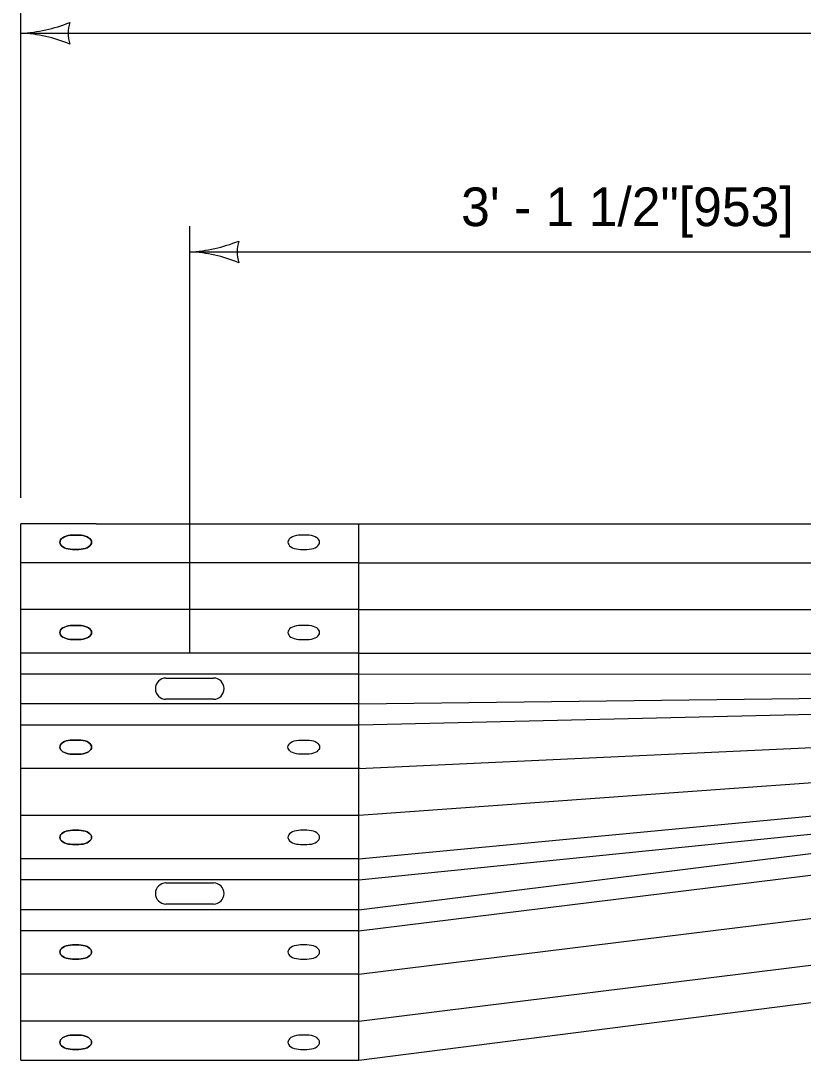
# Model space of a CAD drawing. Extents: x 49991 to 50160, y 49948 to 50051.
# Drawn here: x 50012.117 to 50013.332, y 49992.648 to 49994.263 of the extents above; entities that cross this region are included whole.
import ezdxf

# ---------------------------------------------------------------- set-up
doc = ezdxf.new("R2010")
doc.units = 0
for name, color, linetype in [('Level 1', 7, 'Continuous'), ('Level 2', 7, 'Continuous'), ('Level 3', 7, 'Continuous')]:
    doc.layers.add(name, color=color, linetype=linetype)

msp = doc.modelspace()

# ---------------------------------------------------------------- linework, layer by layer
at = {"layer": 'Level 1'}
for p, q in [((50012.1168, 49992.6481), (50012.1168, 49993.4814)), ((50012.234, 49993.4814), (50015.7668, 49993.4812)), ((50012.6417, 49992.6481), (50012.6417, 49993.4814)), ((50012.207, 49993.4637), (50012.1972, 49993.4637)), ((50012.1972, 49993.4637), (50012.207, 49993.4637)), ((50012.5613, 49993.4637), (50012.5515, 49993.4637)), ((50012.1972, 49993.4416), (50012.207, 49993.4416)), ((50012.207, 49993.4416), (50012.1972, 49993.4416)), ((50012.5515, 49993.4416), (50012.5613, 49993.4416)), ((50012.6417, 49993.4206), (50012.1168, 49993.4206)), ((50012.6417, 49993.4206), (50015.7668, 49993.4206)), ((50012.6417, 49993.3481), (50012.1168, 49993.3481)), ((50012.6417, 49993.3481), (50015.7668, 49993.3478)), ((50012.207, 49993.3235), (50012.1972, 49993.3235)), ((50012.1972, 49993.3235), (50012.207, 49993.3235)), ((50012.5613, 49993.3235), (50012.5515, 49993.3235)), ((50012.1972, 49993.3014), (50012.207, 49993.3014)), ((50012.207, 49993.3014), (50012.1972, 49993.3014)), ((50012.5515, 49993.3014), (50012.5613, 49993.3014)), ((50012.6417, 49993.2803), (50012.1168, 49993.2803)), ((50012.6417, 49993.2803), (50015.7668, 49993.2808)), ((50012.6417, 49993.2477), (50012.1168, 49993.2477)), ((50012.6417, 49993.2477), (50013.8943, 49993.2482)), ((50012.3423, 49993.2417), (50012.4162, 49993.2417)), ((50015.2419, 49993.2294), (50012.6417, 49993.1687)), ((50012.6417, 49993.1011), (50015.2419, 49993.2221)), ((50012.6417, 49993.2014), (50013.8983, 49993.2174)), ((50015.2419, 49993.2146), (50012.6417, 49993.0283)), ((50012.641, 49993.2014), (50012.1168, 49993.2014)), ((50012.4162, 49993.2088), (50012.3423, 49993.2088)), ((50012.6417, 49992.9608), (50015.2419, 49993.2073)), ((50012.6424, 49993.1687), (50012.1168, 49993.1687)), ((50012.6417, 49992.8492), (50015.2419, 49993.1697)), ((50012.1972, 49993.1454), (50012.207, 49993.1454)), ((50012.207, 49993.1454), (50012.1972, 49993.1454)), ((50012.5515, 49993.1454), (50012.5613, 49993.1454)), ((50012.207, 49993.1234), (50012.1972, 49993.1234)), ((50012.1972, 49993.1234), (50012.207, 49993.1234)), ((50012.5613, 49993.1234), (50012.5515, 49993.1234)), ((50012.6417, 49992.7816), (50015.2419, 49993.1024)), ((50012.6437, 49993.1011), (50012.1168, 49993.1011)), ((50012.6417, 49992.928), (50013.8855, 49993.0539)), ((50012.6417, 49992.8819), (50013.896, 49993.0379)), ((50012.6417, 49993.0283), (50012.1168, 49993.0283)), ((50012.6417, 49992.7088), (50015.2419, 49993.0299)), ((50012.207, 49993.0052), (50012.1972, 49993.0052)), ((50012.1972, 49993.0052), (50012.207, 49993.0052)), ((50012.5613, 49993.0052), (50012.5515, 49993.0052)), ((50012.1972, 49992.9832), (50012.207, 49992.9832)), ((50012.207, 49992.9832), (50012.1972, 49992.9832)), ((50012.5515, 49992.9832), (50012.5613, 49992.9832)), ((50012.6417, 49992.6481), (50015.2419, 49992.9795)), ((50012.6417, 49992.9608), (50012.1168, 49992.9608)), ((50012.6417, 49992.928), (50012.1168, 49992.928)), ((50012.3423, 49992.9234), (50012.4162, 49992.9234)), ((50012.6417, 49992.8819), (50012.1168, 49992.8819)), ((50012.4162, 49992.8906), (50012.3423, 49992.8906)), ((50012.6417, 49992.8492), (50012.1168, 49992.8492)), ((50012.207, 49992.8272), (50012.1972, 49992.8272)), ((50012.1972, 49992.8272), (50012.207, 49992.8272)), ((50012.5613, 49992.8272), (50012.5515, 49992.8272)), ((50012.1972, 49992.8051), (50012.207, 49992.8051)), ((50012.207, 49992.8051), (50012.1972, 49992.8051)), ((50012.5515, 49992.8051), (50012.5613, 49992.8051)), ((50012.6417, 49992.7816), (50012.1168, 49992.7816)), ((50012.6417, 49992.7088), (50012.1168, 49992.7088)), ((50012.207, 49992.687), (50012.1972, 49992.687)), ((50012.1972, 49992.687), (50012.207, 49992.687)), ((50012.5613, 49992.687), (50012.5515, 49992.687)), ((50012.1972, 49992.6649), (50012.207, 49992.6649)), ((50012.207, 49992.6649), (50012.1972, 49992.6649)), ((50012.5515, 49992.6649), (50012.5613, 49992.6649))]:
    msp.add_line(p, q, dxfattribs=at)
for points in [[(50012.234, 49993.4814), (50012.1168, 49993.4814)], [(50012.1972, 49993.4637), (50012.1937, 49993.4635), (50012.1904, 49993.463), (50012.1873, 49993.4622), (50012.1845, 49993.4611), (50012.1821, 49993.4597), (50012.1801, 49993.4582), (50012.1787, 49993.4564), (50012.1778, 49993.4546), (50012.1777, 49993.4545)], [(50012.1777, 49993.4545), (50012.1778, 49993.4546), (50012.1787, 49993.4564), (50012.1801, 49993.4582), (50012.1821, 49993.4597), (50012.1845, 49993.4611), (50012.1873, 49993.4622), (50012.1904, 49993.463), (50012.1937, 49993.4635), (50012.1972, 49993.4637)], [(50012.2264, 49993.4545), (50012.2264, 49993.4546), (50012.2255, 49993.4564), (50012.2241, 49993.4582), (50012.2221, 49993.4597), (50012.2197, 49993.4611), (50012.2168, 49993.4622), (50012.2137, 49993.463), (50012.2104, 49993.4635), (50012.207, 49993.4637)], [(50012.207, 49993.4637), (50012.2104, 49993.4635), (50012.2137, 49993.463), (50012.2168, 49993.4622), (50012.2197, 49993.4611), (50012.2221, 49993.4597), (50012.2241, 49993.4582), (50012.2255, 49993.4564), (50012.2264, 49993.4546), (50012.2264, 49993.4545)], [(50012.5515, 49993.4637), (50012.5481, 49993.4635), (50012.5448, 49993.463), (50012.5416, 49993.4622), (50012.5388, 49993.4611), (50012.5364, 49993.4597), (50012.5344, 49993.4582), (50012.533, 49993.4564), (50012.5321, 49993.4546), (50012.5321, 49993.4545)], [(50012.5808, 49993.4545), (50012.5807, 49993.4546), (50012.5798, 49993.4564), (50012.5784, 49993.4582), (50012.5764, 49993.4597), (50012.574, 49993.4611), (50012.5712, 49993.4622), (50012.5681, 49993.463), (50012.5648, 49993.4635), (50012.5613, 49993.4637)], [(50012.1777, 49993.4545), (50012.1775, 49993.4527), (50012.1778, 49993.4507), (50012.1787, 49993.4489), (50012.1801, 49993.4471), (50012.1821, 49993.4456), (50012.1845, 49993.4442), (50012.1873, 49993.4431), (50012.1904, 49993.4423), (50012.1937, 49993.4418), (50012.1972, 49993.4416)], [(50012.1972, 49993.4416), (50012.1937, 49993.4418), (50012.1904, 49993.4423), (50012.1873, 49993.4431), (50012.1845, 49993.4442), (50012.1821, 49993.4456), (50012.1801, 49993.4471), (50012.1787, 49993.4489), (50012.1778, 49993.4507), (50012.1775, 49993.4527), (50012.1777, 49993.4545)], [(50012.207, 49993.4416), (50012.2104, 49993.4418), (50012.2137, 49993.4423), (50012.2168, 49993.4431), (50012.2197, 49993.4442), (50012.2221, 49993.4456), (50012.2241, 49993.4471), (50012.2255, 49993.4489), (50012.2264, 49993.4507), (50012.2267, 49993.4527), (50012.2264, 49993.4545)], [(50012.2264, 49993.4545), (50012.2267, 49993.4527), (50012.2264, 49993.4507), (50012.2255, 49993.4489), (50012.2241, 49993.4471), (50012.2221, 49993.4456), (50012.2197, 49993.4442), (50012.2168, 49993.4431), (50012.2137, 49993.4423), (50012.2104, 49993.4418), (50012.207, 49993.4416)], [(50012.5321, 49993.4545), (50012.5318, 49993.4527), (50012.5321, 49993.4507), (50012.533, 49993.4489), (50012.5344, 49993.4471), (50012.5364, 49993.4456), (50012.5388, 49993.4442), (50012.5416, 49993.4431), (50012.5448, 49993.4423), (50012.5481, 49993.4418), (50012.5515, 49993.4416)], [(50012.5613, 49993.4416), (50012.5648, 49993.4418), (50012.5681, 49993.4423), (50012.5712, 49993.4431), (50012.574, 49993.4442), (50012.5764, 49993.4456), (50012.5784, 49993.4471), (50012.5798, 49993.4489), (50012.5807, 49993.4507), (50012.581, 49993.4527), (50012.5808, 49993.4545)], [(50012.1972, 49993.3235), (50012.1937, 49993.3233), (50012.1904, 49993.3228), (50012.1873, 49993.322), (50012.1845, 49993.3209), (50012.1821, 49993.3195), (50012.1801, 49993.318), (50012.1787, 49993.3162), (50012.1778, 49993.3144), (50012.1775, 49993.3125), (50012.1778, 49993.3105), (50012.1787, 49993.3087), (50012.1801, 49993.3069), (50012.1821, 49993.3054), (50012.1845, 49993.304), (50012.1873, 49993.3029), (50012.1904, 49993.3021), (50012.1937, 49993.3016), (50012.1972, 49993.3014)], [(50012.1972, 49993.3014), (50012.1937, 49993.3016), (50012.1904, 49993.3021), (50012.1873, 49993.3029), (50012.1845, 49993.304), (50012.1821, 49993.3054), (50012.1801, 49993.3069), (50012.1787, 49993.3087), (50012.1778, 49993.3105), (50012.1775, 49993.3125), (50012.1778, 49993.3144), (50012.1787, 49993.3162), (50012.1801, 49993.318), (50012.1821, 49993.3195), (50012.1845, 49993.3209), (50012.1873, 49993.322), (50012.1904, 49993.3228), (50012.1937, 49993.3233), (50012.1972, 49993.3235)], [(50012.207, 49993.3014), (50012.2104, 49993.3016), (50012.2137, 49993.3021), (50012.2168, 49993.3029), (50012.2197, 49993.304), (50012.2221, 49993.3054), (50012.2241, 49993.3069), (50012.2255, 49993.3087), (50012.2264, 49993.3105), (50012.2267, 49993.3125), (50012.2264, 49993.3144), (50012.2255, 49993.3162), (50012.2241, 49993.318), (50012.2221, 49993.3195), (50012.2197, 49993.3209), (50012.2168, 49993.322), (50012.2137, 49993.3228), (50012.2104, 49993.3233), (50012.207, 49993.3235)], [(50012.207, 49993.3235), (50012.2104, 49993.3233), (50012.2137, 49993.3228), (50012.2168, 49993.322), (50012.2197, 49993.3209), (50012.2221, 49993.3195), (50012.2241, 49993.318), (50012.2255, 49993.3162), (50012.2264, 49993.3144), (50012.2267, 49993.3125), (50012.2264, 49993.3105), (50012.2255, 49993.3087), (50012.2241, 49993.3069), (50012.2221, 49993.3054), (50012.2197, 49993.304), (50012.2168, 49993.3029), (50012.2137, 49993.3021), (50012.2104, 49993.3016), (50012.207, 49993.3014)], [(50012.5515, 49993.3235), (50012.5481, 49993.3233), (50012.5448, 49993.3228), (50012.5416, 49993.322), (50012.5388, 49993.3209), (50012.5364, 49993.3195), (50012.5344, 49993.318), (50012.533, 49993.3162), (50012.5321, 49993.3144), (50012.5318, 49993.3125), (50012.5321, 49993.3105), (50012.533, 49993.3087), (50012.5344, 49993.3069), (50012.5364, 49993.3054), (50012.5388, 49993.304), (50012.5416, 49993.3029), (50012.5448, 49993.3021), (50012.5481, 49993.3016), (50012.5515, 49993.3014)], [(50012.5613, 49993.3014), (50012.5648, 49993.3016), (50012.5681, 49993.3021), (50012.5712, 49993.3029), (50012.574, 49993.304), (50012.5764, 49993.3054), (50012.5784, 49993.3069), (50012.5798, 49993.3087), (50012.5807, 49993.3105), (50012.581, 49993.3125), (50012.5807, 49993.3144), (50012.5798, 49993.3162), (50012.5784, 49993.318), (50012.5764, 49993.3195), (50012.574, 49993.3209), (50012.5712, 49993.322), (50012.5681, 49993.3228), (50012.5648, 49993.3233), (50012.5613, 49993.3235)], [(50012.1972, 49993.1234), (50012.1937, 49993.1236), (50012.1904, 49993.1241), (50012.1873, 49993.1249), (50012.1845, 49993.126), (50012.1821, 49993.1273), (50012.1801, 49993.1289), (50012.1787, 49993.1306), (50012.1778, 49993.1325), (50012.1775, 49993.1344), (50012.1777, 49993.1362)], [(50012.1777, 49993.1362), (50012.1775, 49993.1344), (50012.1778, 49993.1325), (50012.1787, 49993.1306), (50012.1801, 49993.1289), (50012.1821, 49993.1273), (50012.1845, 49993.126), (50012.1873, 49993.1249), (50012.1904, 49993.1241), (50012.1937, 49993.1236), (50012.1972, 49993.1234)], [(50012.1777, 49993.1362), (50012.1778, 49993.1363), (50012.1787, 49993.1382), (50012.1801, 49993.1399), (50012.1821, 49993.1415), (50012.1845, 49993.1429), (50012.1873, 49993.144), (50012.1904, 49993.1448), (50012.1937, 49993.1453), (50012.1972, 49993.1454)], [(50012.1972, 49993.1454), (50012.1937, 49993.1453), (50012.1904, 49993.1448), (50012.1873, 49993.144), (50012.1845, 49993.1429), (50012.1821, 49993.1415), (50012.1801, 49993.1399), (50012.1787, 49993.1382), (50012.1778, 49993.1363), (50012.1777, 49993.1362)], [(50012.207, 49993.1454), (50012.2104, 49993.1453), (50012.2137, 49993.1448), (50012.2168, 49993.144), (50012.2197, 49993.1429), (50012.2221, 49993.1415), (50012.2241, 49993.1399), (50012.2255, 49993.1382), (50012.2264, 49993.1363), (50012.2264, 49993.1362)], [(50012.2264, 49993.1362), (50012.2264, 49993.1363), (50012.2255, 49993.1382), (50012.2241, 49993.1399), (50012.2221, 49993.1415), (50012.2197, 49993.1429), (50012.2168, 49993.144), (50012.2137, 49993.1448), (50012.2104, 49993.1453), (50012.207, 49993.1454)], [(50012.2264, 49993.1362), (50012.2267, 49993.1344), (50012.2264, 49993.1325), (50012.2255, 49993.1306), (50012.2241, 49993.1289), (50012.2221, 49993.1273), (50012.2197, 49993.126), (50012.2168, 49993.1249), (50012.2137, 49993.1241), (50012.2104, 49993.1236), (50012.207, 49993.1234)], [(50012.207, 49993.1234), (50012.2104, 49993.1236), (50012.2137, 49993.1241), (50012.2168, 49993.1249), (50012.2197, 49993.126), (50012.2221, 49993.1273), (50012.2241, 49993.1289), (50012.2255, 49993.1306), (50012.2264, 49993.1325), (50012.2267, 49993.1344), (50012.2264, 49993.1362)], [(50012.5515, 49993.1234), (50012.5481, 49993.1236), (50012.5448, 49993.1241), (50012.5416, 49993.1249), (50012.5388, 49993.126), (50012.5364, 49993.1273), (50012.5344, 49993.1289), (50012.533, 49993.1306), (50012.5321, 49993.1325), (50012.5318, 49993.1344), (50012.5321, 49993.1362)], [(50012.5321, 49993.1362), (50012.5321, 49993.1363), (50012.533, 49993.1382), (50012.5344, 49993.1399), (50012.5364, 49993.1415), (50012.5388, 49993.1429), (50012.5416, 49993.144), (50012.5448, 49993.1448), (50012.5481, 49993.1453), (50012.5515, 49993.1454)], [(50012.5613, 49993.1454), (50012.5648, 49993.1453), (50012.5681, 49993.1448), (50012.5712, 49993.144), (50012.574, 49993.1429), (50012.5764, 49993.1415), (50012.5784, 49993.1399), (50012.5798, 49993.1382), (50012.5807, 49993.1363), (50012.5808, 49993.1362)], [(50012.5808, 49993.1362), (50012.581, 49993.1344), (50012.5807, 49993.1325), (50012.5798, 49993.1306), (50012.5784, 49993.1289), (50012.5764, 49993.1273), (50012.574, 49993.126), (50012.5712, 49993.1249), (50012.5681, 49993.1241), (50012.5648, 49993.1236), (50012.5613, 49993.1234)], [(50012.1972, 49993.0052), (50012.1937, 49993.0051), (50012.1904, 49993.0046), (50012.1873, 49993.0038), (50012.1845, 49993.0027), (50012.1821, 49993.0013), (50012.1801, 49992.9997), (50012.1787, 49992.998), (50012.1778, 49992.9961), (50012.1775, 49992.9942), (50012.1778, 49992.9923), (50012.1787, 49992.9904), (50012.1801, 49992.9887), (50012.1821, 49992.9871), (50012.1845, 49992.9858), (50012.1873, 49992.9847), (50012.1904, 49992.9839), (50012.1937, 49992.9834), (50012.1972, 49992.9832)], [(50012.1972, 49992.9832), (50012.1937, 49992.9834), (50012.1904, 49992.9839), (50012.1873, 49992.9847), (50012.1845, 49992.9858), (50012.1821, 49992.9871), (50012.1801, 49992.9887), (50012.1787, 49992.9904), (50012.1778, 49992.9923), (50012.1775, 49992.9942), (50012.1778, 49992.9961), (50012.1787, 49992.998), (50012.1801, 49992.9997), (50012.1821, 49993.0013), (50012.1845, 49993.0027), (50012.1873, 49993.0038), (50012.1904, 49993.0046), (50012.1937, 49993.0051), (50012.1972, 49993.0052)], [(50012.207, 49992.9832), (50012.2104, 49992.9834), (50012.2137, 49992.9839), (50012.2168, 49992.9847), (50012.2197, 49992.9858), (50012.2221, 49992.9871), (50012.2241, 49992.9887), (50012.2255, 49992.9904), (50012.2264, 49992.9923), (50012.2267, 49992.9942), (50012.2264, 49992.9961), (50012.2255, 49992.998), (50012.2241, 49992.9997), (50012.2221, 49993.0013), (50012.2197, 49993.0027), (50012.2168, 49993.0038), (50012.2137, 49993.0046), (50012.2104, 49993.0051), (50012.207, 49993.0052)], [(50012.207, 49993.0052), (50012.2104, 49993.0051), (50012.2137, 49993.0046), (50012.2168, 49993.0038), (50012.2197, 49993.0027), (50012.2221, 49993.0013), (50012.2241, 49992.9997), (50012.2255, 49992.998), (50012.2264, 49992.9961), (50012.2267, 49992.9942), (50012.2264, 49992.9923), (50012.2255, 49992.9904), (50012.2241, 49992.9887), (50012.2221, 49992.9871), (50012.2197, 49992.9858), (50012.2168, 49992.9847), (50012.2137, 49992.9839), (50012.2104, 49992.9834), (50012.207, 49992.9832)], [(50012.5515, 49993.0052), (50012.5481, 49993.0051), (50012.5448, 49993.0046), (50012.5416, 49993.0038), (50012.5388, 49993.0027), (50012.5364, 49993.0013), (50012.5344, 49992.9997), (50012.533, 49992.998), (50012.5321, 49992.9961), (50012.5318, 49992.9942), (50012.5321, 49992.9923), (50012.533, 49992.9904), (50012.5344, 49992.9887), (50012.5364, 49992.9871), (50012.5388, 49992.9858), (50012.5416, 49992.9847), (50012.5448, 49992.9839), (50012.5481, 49992.9834), (50012.5515, 49992.9832)], [(50012.5613, 49992.9832), (50012.5648, 49992.9834), (50012.5681, 49992.9839), (50012.5712, 49992.9847), (50012.574, 49992.9858), (50012.5764, 49992.9871), (50012.5784, 49992.9887), (50012.5798, 49992.9904), (50012.5807, 49992.9923), (50012.581, 49992.9942), (50012.5807, 49992.9961), (50012.5798, 49992.998), (50012.5784, 49992.9997), (50012.5764, 49993.0013), (50012.574, 49993.0027), (50012.5712, 49993.0038), (50012.5681, 49993.0046), (50012.5648, 49993.0051), (50012.5613, 49993.0052)], [(50012.1972, 49992.8272), (50012.1937, 49992.827), (50012.1904, 49992.8265), (50012.1873, 49992.8257), (50012.1845, 49992.8246), (50012.1821, 49992.8233), (50012.1801, 49992.8217), (50012.1787, 49992.8199), (50012.1778, 49992.8181), (50012.1777, 49992.818)], [(50012.1777, 49992.818), (50012.1778, 49992.8181), (50012.1787, 49992.8199), (50012.1801, 49992.8217), (50012.1821, 49992.8233), (50012.1845, 49992.8246), (50012.1873, 49992.8257), (50012.1904, 49992.8265), (50012.1937, 49992.827), (50012.1972, 49992.8272)], [(50012.2264, 49992.818), (50012.2264, 49992.8181), (50012.2255, 49992.8199), (50012.2241, 49992.8217), (50012.2221, 49992.8233), (50012.2197, 49992.8246), (50012.2168, 49992.8257), (50012.2137, 49992.8265), (50012.2104, 49992.827), (50012.207, 49992.8272)], [(50012.207, 49992.8272), (50012.2104, 49992.827), (50012.2137, 49992.8265), (50012.2168, 49992.8257), (50012.2197, 49992.8246), (50012.2221, 49992.8233), (50012.2241, 49992.8217), (50012.2255, 49992.8199), (50012.2264, 49992.8181), (50012.2264, 49992.818)], [(50012.5515, 49992.8272), (50012.5481, 49992.827), (50012.5448, 49992.8265), (50012.5416, 49992.8257), (50012.5388, 49992.8246), (50012.5364, 49992.8233), (50012.5344, 49992.8217), (50012.533, 49992.8199), (50012.5321, 49992.8181), (50012.5321, 49992.818)], [(50012.5808, 49992.818), (50012.5807, 49992.8181), (50012.5798, 49992.8199), (50012.5784, 49992.8217), (50012.5764, 49992.8233), (50012.574, 49992.8246), (50012.5712, 49992.8257), (50012.5681, 49992.8265), (50012.5648, 49992.827), (50012.5613, 49992.8272)], [(50012.1777, 49992.818), (50012.1775, 49992.8162), (50012.1778, 49992.8143), (50012.1787, 49992.8124), (50012.1801, 49992.8107), (50012.1821, 49992.8091), (50012.1845, 49992.8077), (50012.1873, 49992.8066), (50012.1904, 49992.8058), (50012.1937, 49992.8053), (50012.1972, 49992.8051)], [(50012.1972, 49992.8051), (50012.1937, 49992.8053), (50012.1904, 49992.8058), (50012.1873, 49992.8066), (50012.1845, 49992.8077), (50012.1821, 49992.8091), (50012.1801, 49992.8107), (50012.1787, 49992.8124), (50012.1778, 49992.8143), (50012.1775, 49992.8162), (50012.1777, 49992.818)], [(50012.207, 49992.8051), (50012.2104, 49992.8053), (50012.2137, 49992.8058), (50012.2168, 49992.8066), (50012.2197, 49992.8077), (50012.2221, 49992.8091), (50012.2241, 49992.8107), (50012.2255, 49992.8124), (50012.2264, 49992.8143), (50012.2267, 49992.8162), (50012.2264, 49992.818)], [(50012.2264, 49992.818), (50012.2267, 49992.8162), (50012.2264, 49992.8143), (50012.2255, 49992.8124), (50012.2241, 49992.8107), (50012.2221, 49992.8091), (50012.2197, 49992.8077), (50012.2168, 49992.8066), (50012.2137, 49992.8058), (50012.2104, 49992.8053), (50012.207, 49992.8051)], [(50012.5321, 49992.818), (50012.5318, 49992.8162), (50012.5321, 49992.8143), (50012.533, 49992.8124), (50012.5344, 49992.8107), (50012.5364, 49992.8091), (50012.5388, 49992.8077), (50012.5416, 49992.8066), (50012.5448, 49992.8058), (50012.5481, 49992.8053), (50012.5515, 49992.8051)], [(50012.5613, 49992.8051), (50012.5648, 49992.8053), (50012.5681, 49992.8058), (50012.5712, 49992.8066), (50012.574, 49992.8077), (50012.5764, 49992.8091), (50012.5784, 49992.8107), (50012.5798, 49992.8124), (50012.5807, 49992.8143), (50012.581, 49992.8162), (50012.5808, 49992.818)], [(50012.1972, 49992.687), (50012.1937, 49992.6868), (50012.1904, 49992.6863), (50012.1873, 49992.6855), (50012.1845, 49992.6844), (50012.1821, 49992.6831), (50012.1801, 49992.6815), (50012.1787, 49992.6797), (50012.1778, 49992.6779), (50012.1775, 49992.676), (50012.1778, 49992.6741), (50012.1787, 49992.6722), (50012.1801, 49992.6705), (50012.1821, 49992.6689), (50012.1845, 49992.6675), (50012.1873, 49992.6664), (50012.1904, 49992.6656), (50012.1937, 49992.6651), (50012.1972, 49992.6649)], [(50012.1972, 49992.6649), (50012.1937, 49992.6651), (50012.1904, 49992.6656), (50012.1873, 49992.6664), (50012.1845, 49992.6675), (50012.1821, 49992.6689), (50012.1801, 49992.6705), (50012.1787, 49992.6722), (50012.1778, 49992.6741), (50012.1775, 49992.676), (50012.1778, 49992.6779), (50012.1787, 49992.6797), (50012.1801, 49992.6815), (50012.1821, 49992.6831), (50012.1845, 49992.6844), (50012.1873, 49992.6855), (50012.1904, 49992.6863), (50012.1937, 49992.6868), (50012.1972, 49992.687)], [(50012.207, 49992.6649), (50012.2104, 49992.6651), (50012.2137, 49992.6656), (50012.2168, 49992.6664), (50012.2197, 49992.6675), (50012.2221, 49992.6689), (50012.2241, 49992.6705), (50012.2255, 49992.6722), (50012.2264, 49992.6741), (50012.2267, 49992.676), (50012.2264, 49992.6779), (50012.2255, 49992.6797), (50012.2241, 49992.6815), (50012.2221, 49992.6831), (50012.2197, 49992.6844), (50012.2168, 49992.6855), (50012.2137, 49992.6863), (50012.2104, 49992.6868), (50012.207, 49992.687)], [(50012.207, 49992.687), (50012.2104, 49992.6868), (50012.2137, 49992.6863), (50012.2168, 49992.6855), (50012.2197, 49992.6844), (50012.2221, 49992.6831), (50012.2241, 49992.6815), (50012.2255, 49992.6797), (50012.2264, 49992.6779), (50012.2267, 49992.676), (50012.2264, 49992.6741), (50012.2255, 49992.6722), (50012.2241, 49992.6705), (50012.2221, 49992.6689), (50012.2197, 49992.6675), (50012.2168, 49992.6664), (50012.2137, 49992.6656), (50012.2104, 49992.6651), (50012.207, 49992.6649)], [(50012.5515, 49992.687), (50012.5481, 49992.6868), (50012.5448, 49992.6863), (50012.5416, 49992.6855), (50012.5388, 49992.6844), (50012.5364, 49992.6831), (50012.5344, 49992.6815), (50012.533, 49992.6797), (50012.5321, 49992.6779), (50012.5318, 49992.676), (50012.5321, 49992.6741), (50012.533, 49992.6722), (50012.5344, 49992.6705), (50012.5364, 49992.6689), (50012.5388, 49992.6675), (50012.5416, 49992.6664), (50012.5448, 49992.6656), (50012.5481, 49992.6651), (50012.5515, 49992.6649)], [(50012.5613, 49992.6649), (50012.5648, 49992.6651), (50012.5681, 49992.6656), (50012.5712, 49992.6664), (50012.574, 49992.6675), (50012.5764, 49992.6689), (50012.5784, 49992.6705), (50012.5798, 49992.6722), (50012.5807, 49992.6741), (50012.581, 49992.676), (50012.5807, 49992.6779), (50012.5798, 49992.6797), (50012.5784, 49992.6815), (50012.5764, 49992.6831), (50012.574, 49992.6844), (50012.5712, 49992.6855), (50012.5681, 49992.6863), (50012.5648, 49992.6868), (50012.5613, 49992.687)], [(50012.1168, 49992.6481), (50012.6417, 49992.6481)]]:
    msp.add_lwpolyline(points, dxfattribs=at)
for centre, start, end in [((50012.3423, 49993.2252), 90, 270), ((50012.4162, 49993.2252), 270, 90), ((50012.3423, 49992.907), 90, 270), ((50012.4162, 49992.907), 270, 90)]:
    msp.add_arc(centre, 0.0164, start, end, dxfattribs=at)
at = {"layer": 'Level 3'}
for p, q in [((50012.1168, 49993.5214), (50012.1168, 49994.2833)), ((50012.1168, 49994.2433), (50015.7668, 49994.2433)), ((50012.3792, 49993.2817), (50012.3792, 49993.9437)), ((50012.3792, 49993.9037), (50013.9388, 49993.9037))]:
    msp.add_line(p, q, dxfattribs=at)
for centre, radius, start, end in [((50012.1053, 49994.476), 0.233, 272.8273, 292.0772), ((50012.245, 49994.2433), 0.0548, 162.1388, 197.8612), ((50012.1076, 49994.0212), 0.2223, 67.456, 87.6395), ((50012.3678, 49994.1364), 0.233, 272.8273, 292.0772), ((50012.5075, 49993.9037), 0.0548, 162.1388, 197.8612), ((50012.3701, 49993.6816), 0.2223, 67.456, 87.6395)]:
    msp.add_arc(centre, radius, start, end, dxfattribs=at)

# ---------------------------------------------------------------- texts
at = {"layer": 'Level 2'}
msp.add_text('3\' - 1 1/2"[953]', height=0.06, dxfattribs=at).set_placement((50012.8007, 49993.9437))

doc.saveas('drawing.dxf')
